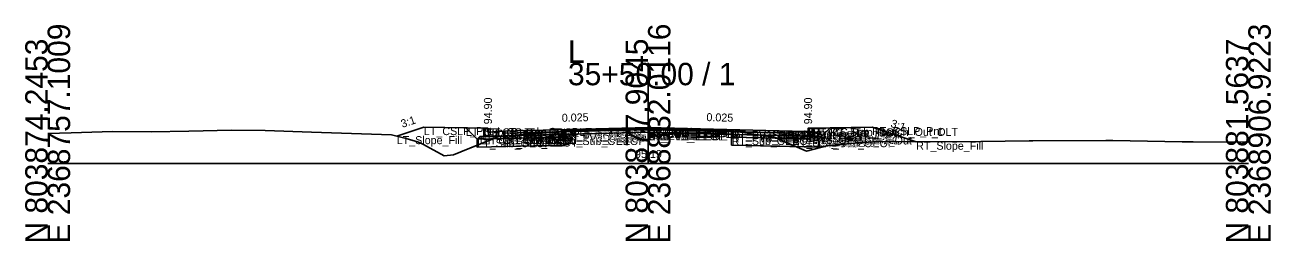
# Model space of a CAD drawing. Extents: x -26 to 8153, y -10 to 9520.
# Drawn here: x 2997.2 to 3152.8, y 990.3 to 1017.3 of the extents above; entities that cross this region are included whole.
import ezdxf

# ---------------------------------------------------------------- set-up
doc = ezdxf.new("R2010")
doc.units = 0
for name, color, linetype in [('Exist CMT Pavement', 7, 'Continuous'), ('Exist Cross Section Cell', 7, 'Continuous'), ('Exist XS Center Line Elevation Label', 7, 'Continuous'), ('Exist XS Ground Line', 7, 'Continuous'), ('Prop CMT Conc Surface', 7, 'Continuous'), ('Prop CMT Concrete Structures', 7, 'Continuous'), ('Prop CMT Pvmt Course 1', 7, 'Continuous'), ('Prop CMT Pvmt Course 1 CG', 7, 'Continuous'), ('Prop CMT Pvmt Course 1 Wedge', 7, 'Continuous'), ('Prop CMT Pvmt Course 2', 7, 'Continuous'), ('Prop CMT Pvmt Course 2 Wedge', 7, 'Continuous'), ('Prop CMT Pvmt Course 3', 7, 'Continuous'), ('Prop CMT Pvmt Course 3 Wedge', 7, 'Continuous'), ('Prop CMT Pvmt Surface', 7, 'Continuous'), ('Prop CMT Pvmt Wedge Surface 1', 7, 'Continuous'), ('Prop CMT Pvmt Wedge Surface 2', 7, 'Continuous'), ('Prop CMT Pvmt Wedge Surface 3', 7, 'Continuous'), ('Prop CMT Shallow Undercut', 7, 'Continuous'), ('Prop CMT Shallow Undercut Boundary', 7, 'Continuous'), ('Prop CMT Slope Grass', 7, 'Continuous'), ('Prop CMT Subgrade Earthwork', 7, 'Continuous'), ('Prop XS Earthwork Shape', 7, 'Continuous'), ('Prop XS Hydro Elevations', 7, 'Continuous'), ('Prop XS SE Text', 7, 'Continuous'), ('Prop XS Side Slope Text', 7, 'Continuous'), ('Prop XS Subgrade Earthwork', 7, 'Continuous'), ('Scratch_Level_2', 7, 'Continuous'), ('Scratch_Level_6', 7, 'Continuous')]:
    doc.layers.add(name, color=color, linetype=linetype)

msp = doc.modelspace()

# ---------------------------------------------------------------- linework, layer by layer
at = {"layer": 'Exist CMT Pavement'}
for p, q in [((3067.61, 1004.07), (3074.8, 1004.19)), ((3074.8, 1004.19), (3079.84, 1004.14)), ((3064.5, 1004.02), (3067.61, 1004.07)), ((3079.84, 1004.14), (3085.45, 1004.1))]:
    msp.add_line(p, q, dxfattribs=at)
at = {"layer": 'Exist Cross Section Cell'}
for p, q in [((3075, 1000), (3075, 1012.58)), ((3000, 1000), (3075, 1000)), ((3075, 1000), (3150, 1000))]:
    msp.add_line(p, q, dxfattribs=at)
at = {"layer": 'Exist XS Ground Line'}
for p, q in [((3017.62, 1004.05), (3022.95, 1004.16)), ((3022.95, 1004.16), (3027.17, 1004.12)), ((3067.61, 1004.07), (3074.8, 1004.19)), ((3074.8, 1004.19), (3079.84, 1004.14)), ((3000, 1003.75), (3002.92, 1003.84)), ((3002.92, 1003.84), (3008.08, 1003.98)), ((3008.08, 1003.98), (3012.94, 1003.94)), ((3012.94, 1003.94), (3017.62, 1004.05)), ((3027.17, 1004.12), (3032.96, 1003.91)), ((3032.96, 1003.91), (3036.72, 1003.78)), ((3036.72, 1003.78), (3042.97, 1003.59)), ((3042.97, 1003.59), (3044.78, 1003.11)), ((3044.78, 1003.11), (3046.32, 1002.68)), ((3046.32, 1002.68), (3046.95, 1002.36)), ((3051.6, 1001.44), (3056.37, 1003.39)), ((3056.37, 1003.39), (3059.85, 1003.68)), ((3059.85, 1003.68), (3064.5, 1004.02)), ((3064.5, 1004.02), (3067.61, 1004.07)), ((3079.84, 1004.14), (3085.45, 1004.1)), ((3085.45, 1004.1), (3087.95, 1003.72)), ((3087.95, 1003.72), (3090.8, 1003.31)), ((3090.8, 1003.31), (3092.17, 1002.65)), ((3092.17, 1002.65), (3094.8, 1001.55)), ((3101.3, 1002.58), (3103.05, 1002.72)), ((3103.05, 1002.72), (3103.54, 1002.74)), ((3103.54, 1002.74), (3113.06, 1002.7)), ((3113.06, 1002.7), (3113.6, 1002.71)), ((3113.6, 1002.71), (3122.63, 1002.83)), ((3122.63, 1002.83), (3123.07, 1002.83)), ((3123.07, 1002.83), (3132.18, 1002.86)), ((3132.18, 1002.86), (3133.09, 1002.87)), ((3133.09, 1002.87), (3141.72, 1002.72)), ((3141.72, 1002.72), (3143.1, 1002.71)), ((3143.1, 1002.71), (3150, 1002.68)), ((3046.95, 1002.36), (3047.31, 1002.18)), ((3047.31, 1002.18), (3049.53, 1000.94)), ((3049.53, 1000.94), (3050.72, 1001.09)), ((3050.72, 1001.09), (3051.6, 1001.44)), ((3094.8, 1001.55), (3097.51, 1002.26)), ((3097.51, 1002.26), (3101.3, 1002.58))]:
    msp.add_line(p, q, dxfattribs=at)
at = {"layer": 'Prop CMT Conc Surface'}
for points in [[(3055, 1003.9), (3055, 1004.4), (3054.5, 1004.4)], [(3095, 1003.9), (3095, 1004.4), (3095.5, 1004.4)], [(3057, 1004.03), (3055, 1003.9)], [(3093, 1004.03), (3095, 1003.9)]]:
    msp.add_lwpolyline(points, dxfattribs=at)
at = {"layer": 'Prop CMT Concrete Structures'}
for points in [[(3057, 1004.03), (3055, 1003.9), (3055, 1004.4), (3054.5, 1004.4)], [(3054.5, 1004.4), (3054.5, 1003.39), (3057, 1003.45)], [(3093, 1004.03), (3095, 1003.9), (3095, 1004.4), (3095.5, 1004.4)], [(3095.5, 1004.4), (3095.5, 1003.39), (3093, 1003.45)], [(3057, 1003.45), (3057, 1004.03)], [(3093, 1003.45), (3093, 1004.03)]]:
    msp.add_lwpolyline(points, dxfattribs=at)
at = {"layer": 'Prop CMT Pvmt Course 1'}
for points in [[(3075, 1004.48), (3057, 1004.03)], [(3064.5, 1004.1), (3075, 1004.36)], [(3075, 1004.23), (3075, 1004.48)], [(3075, 1004.48), (3093, 1004.03)], [(3075, 1004.23), (3075, 1004.48)], [(3075, 1004.36), (3075, 1004.23), (3075, 1004.23)], [(3085.45, 1004.1), (3075, 1004.36)], [(3075, 1004.36), (3075, 1004.23), (3075, 1004.23)], [(3057, 1004.03), (3057, 1003.78)], [(3057, 1003.78), (3064.5, 1003.97)], [(3064.5, 1003.97), (3064.5, 1004.1)], [(3085.45, 1003.97), (3085.45, 1004.1)], [(3093, 1003.78), (3085.45, 1003.97)], [(3093, 1004.03), (3093, 1003.78)]]:
    msp.add_lwpolyline(points, dxfattribs=at)
at = {"layer": 'Prop CMT Pvmt Course 1 CG'}
for points in [[(3057, 1003.45), (3054, 1003.38), (3053.66, 1003.04)], [(3053.66, 1003.04), (3057, 1003.12)], [(3057, 1003.12), (3057, 1003.45)], [(3093, 1003.45), (3096, 1003.38), (3096.34, 1003.04)], [(3093, 1003.12), (3093, 1003.45)], [(3096.34, 1003.04), (3093, 1003.12)]]:
    msp.add_lwpolyline(points, dxfattribs=at)
at = {"layer": 'Prop CMT Pvmt Course 1 Wedge'}
for points in [[(3075, 1004.36), (3064.5, 1004.1)], [(3075, 1004.36), (3085.45, 1004.1)]]:
    msp.add_lwpolyline(points, dxfattribs=at)
at = {"layer": 'Prop CMT Pvmt Course 2'}
for points in [[(3064.5, 1003.97), (3057, 1003.78)], [(3057, 1003.78), (3057, 1003.45)], [(3057, 1003.45), (3064.5, 1003.64)], [(3064.5, 1003.64), (3064.5, 1003.97)], [(3085.45, 1003.64), (3085.45, 1003.97)], [(3085.45, 1003.97), (3093, 1003.78)], [(3093, 1003.45), (3085.45, 1003.64)], [(3093, 1003.78), (3093, 1003.45)]]:
    msp.add_lwpolyline(points, dxfattribs=at)
at = {"layer": 'Prop CMT Pvmt Course 2 Wedge'}
for points in [[(3075, 1004.23), (3064.5, 1003.97)], [(3075, 1004.23), (3085.45, 1003.97)]]:
    msp.add_lwpolyline(points, dxfattribs=at)
at = {"layer": 'Prop CMT Pvmt Course 3'}
for points in [[(3064.5, 1003.64), (3057, 1003.45)], [(3057, 1003.45), (3057, 1003.12)], [(3057, 1003.12), (3064.5, 1003.31)], [(3064.5, 1003.31), (3064.5, 1003.64)], [(3085.45, 1003.64), (3093, 1003.45)], [(3085.45, 1003.31), (3085.45, 1003.64)], [(3093, 1003.12), (3085.45, 1003.31)], [(3093, 1003.45), (3093, 1003.12)]]:
    msp.add_lwpolyline(points, dxfattribs=at)
at = {"layer": 'Prop CMT Pvmt Course 3 Wedge'}
for points in [[(3075, 1003.9), (3064.5, 1003.64)], [(3075, 1003.9), (3085.45, 1003.64)]]:
    msp.add_lwpolyline(points, dxfattribs=at)
at = {"layer": 'Prop CMT Pvmt Surface'}
for points in [[(3075, 1004.48), (3057, 1004.03)], [(3075, 1004.48), (3093, 1004.03)]]:
    msp.add_lwpolyline(points, dxfattribs=at)
at = {"layer": 'Prop CMT Pvmt Wedge Surface 1'}
for points in [[(3075, 1004.36), (3064.5, 1004.1)], [(3075, 1004.36), (3085.45, 1004.1)], [(3057, 1003.78), (3057, 1004.03)], [(3064.5, 1003.97), (3057, 1003.78)], [(3064.5, 1004.1), (3064.5, 1003.97)], [(3085.45, 1004.1), (3085.45, 1003.97)], [(3085.45, 1003.97), (3093, 1003.78)], [(3093, 1003.78), (3093, 1004.03)]]:
    msp.add_lwpolyline(points, dxfattribs=at)
at = {"layer": 'Prop CMT Pvmt Wedge Surface 2'}
for points in [[(3075, 1004.23), (3057, 1003.78)], [(3075, 1004.23), (3093, 1003.78)], [(3057, 1003.78), (3057, 1004.03)], [(3093, 1003.78), (3093, 1004.03)]]:
    msp.add_lwpolyline(points, dxfattribs=at)
at = {"layer": 'Prop CMT Pvmt Wedge Surface 3'}
for points in [[(3057, 1003.45), (3057, 1004.03)], [(3075, 1003.9), (3057, 1003.45)], [(3075, 1003.9), (3093, 1003.45)], [(3093, 1003.45), (3093, 1004.03)]]:
    msp.add_lwpolyline(points, dxfattribs=at)
at = {"layer": 'Prop CMT Shallow Undercut'}
for points in [[(3064.5, 1002.31), (3064.5, 1003.31), (3055.64, 1003.09), (3053.66, 1002.28), (3053.66, 1002.04)], [(3092.17, 1002.65), (3093.47, 1002.11), (3085.45, 1002.31), (3085.45, 1003.31), (3091.1, 1003.17)]]:
    msp.add_lwpolyline(points, close=True, dxfattribs=at)
at = {"layer": 'Prop CMT Shallow Undercut Boundary'}
for p, q in [((3053.66, 1003.04), (3064.5, 1003.31)), ((3053.66, 1003.04), (3053.66, 1002.04)), ((3064.5, 1002.31), (3064.5, 1003.31)), ((3085.45, 1003.31), (3085.45, 1002.31)), ((3085.45, 1003.31), (3096.34, 1003.04)), ((3096.34, 1002.04), (3096.34, 1003.04)), ((3053.66, 1002.04), (3064.5, 1002.31)), ((3085.45, 1002.31), (3096.34, 1002.04))]:
    msp.add_line(p, q, dxfattribs=at)
at = {"layer": 'Prop CMT Slope Grass'}
for points in [[(3054.5, 1004.4), (3047, 1004.55), (3043.61, 1003.42)], [(3095.5, 1004.4), (3103, 1004.55), (3108.5, 1002.72)]]:
    msp.add_lwpolyline(points, dxfattribs=at)
at = {"layer": 'Prop CMT Subgrade Earthwork'}
for points in [[(3057, 1003.12), (3053.66, 1003.04), (3052.25, 1004.45)], [(3093, 1003.12), (3096.34, 1003.04), (3097.75, 1004.45)], [(3064.5, 1003.31), (3057, 1003.12)], [(3064.5, 1003.31), (3064.52, 1004.02)], [(3085.45, 1003.31), (3085.44, 1004.1)], [(3085.45, 1003.31), (3093, 1003.12)]]:
    msp.add_lwpolyline(points, dxfattribs=at)
at = {"layer": 'Prop XS Earthwork Shape'}
for points in [[(3052.25, 1004.45), (3047, 1004.55), (3043.61, 1003.42), (3044.78, 1003.11), (3046.32, 1002.68), (3046.95, 1002.36), (3047.31, 1002.18), (3049.53, 1000.94), (3050.72, 1001.09), (3051.6, 1001.44), (3053.66, 1002.28), (3053.66, 1003.04)], [(3093.47, 1002.11), (3094.8, 1001.55), (3097.51, 1002.26), (3101.3, 1002.58), (3103.05, 1002.72), (3103.54, 1002.74), (3108.5, 1002.72), (3103, 1004.55), (3097.75, 1004.45), (3096.34, 1003.04), (3096.34, 1002.04)], [(3053.66, 1002.28), (3055.64, 1003.09), (3057, 1003.12), (3064.5, 1003.31), (3064.5, 1002.31), (3053.66, 1002.04)], [(3053.66, 1002.28), (3055.64, 1003.09), (3053.66, 1003.04)], [(3064.5, 1003.31), (3057, 1003.12), (3055.64, 1003.09), (3056.37, 1003.39), (3059.85, 1003.68), (3064.5, 1004.02), (3064.52, 1004.02)], [(3085.45, 1003.31), (3091.1, 1003.17), (3090.8, 1003.31), (3087.95, 1003.72), (3085.45, 1004.1), (3085.44, 1004.1)], [(3085.45, 1003.31), (3091.1, 1003.17), (3092.17, 1002.65), (3093.47, 1002.11), (3085.45, 1002.31)], [(3093.47, 1002.11), (3096.34, 1002.04), (3096.34, 1003.04), (3093, 1003.12), (3091.1, 1003.17), (3092.17, 1002.65)]]:
    msp.add_lwpolyline(points, close=True, dxfattribs=at)
at = {"layer": 'Prop XS Subgrade Earthwork'}
for p, q in [((3053.66, 1003.04), (3064.5, 1003.31)), ((3085.45, 1003.31), (3096.34, 1003.04))]:
    msp.add_line(p, q, dxfattribs=at)
at = {"layer": 'Scratch_Level_6'}
for points in [[(3064.5, 1002.31), (3064.5, 1003.31), (3055.64, 1003.09), (3053.66, 1002.28), (3053.66, 1002.04)], [(3092.17, 1002.65), (3093.47, 1002.11), (3085.45, 1002.31), (3085.45, 1003.31), (3091.1, 1003.17)]]:
    msp.add_lwpolyline(points, close=True, dxfattribs=at)

# ---------------------------------------------------------------- texts
at = {"layer": 'Exist Cross Section Cell'}
for s, p in [('E 2368757.1009', (3002.8, 990)), ('E 2368832.0116', (3077.8, 990)), ('E 2368906.9223', (3152.8, 990)), ('N 803874.2453', (3000, 990)), ('N 803877.9045', (3075, 990)), ('N 803881.5637', (3150, 990))]:
    msp.add_text(s, height=2.8, rotation=90, dxfattribs=at).set_placement(p)
for s, p in [('L', (3065, 1012.58)), ('35+50.00 / 1', (3065, 1009.78))]:
    msp.add_text(s, height=2.8, dxfattribs=at).set_placement(p)
at = {"layer": 'Exist XS Center Line Elevation Label'}
msp.add_text('95.19', height=1, dxfattribs=at).set_placement((3073.38, 1000.69))
at = {"layer": 'Prop XS Hydro Elevations'}
for p in [(3055.5, 1004.9), (3095.5, 1004.9)]:
    msp.add_text('94.90', height=1, rotation=90, dxfattribs=at).set_placement(p)
at = {"layer": 'Prop XS SE Text'}
for rotation, p in [(1.4321, (3064.24, 1005.21)), (358.5679, (3082.29, 1005.3))]:
    msp.add_text('0.025', height=1, rotation=rotation, dxfattribs=at).set_placement(p)
at = {"layer": 'Prop XS Side Slope Text'}
for rotation, p in [(18.4349, (3044.31, 1004.45)), (341.5651, (3105.23, 1004.6))]:
    msp.add_text('3:1', height=1, rotation=rotation, dxfattribs=at).set_placement(p)
at = {"layer": 'Scratch_Level_2'}
for s, p in [('LT_CSLP_Pnt', (3047, 1003.55)), ('LT_Sub_Trench_Out_DLT', (3052.25, 1003.45)), ('LT_CG_Top_BOC', (3054.5, 1003.4)), ('LT_CG_Top_Face', (3055, 1003.4)), ('PV1_PGL', (3075, 1003.48)), ('RT_PV1_IEEOP', (3075, 1003.36)), ('LT_PV1_IEEOP', (3075, 1003.36)), ('RT_PV2_IEEOP', (3075, 1003.23)), ('LT_PV2_IEEOP', (3075, 1003.23)), ('PV2_PGL', (3075, 1003.23)), ('RT_PV_IEEOP_EG', (3075, 1003.19)), ('LT_PV_IEEOP_EG', (3075, 1003.19)), ('RT_PV_Sub_Tie_Out', (3085.44, 1003.1)), ('RT_CG_Top_Face', (3095, 1003.4)), ('RT_CG_Top_BOC', (3095.5, 1003.4)), ('RT_Sub_Trench_Out_DLT', (3097.75, 1003.45)), ('RT_CSLP_Pnt', (3103, 1003.55)), ('LT_Slope_Fill', (3043.61, 1002.42)), ('LT_Sub_OEOP', (3053.66, 1002.04)), ('LT_CG1_Shelf_Out', (3054, 1002.38)), ('LT_CG_Bot_BOC', (3054.5, 1002.39)), ('LT_CG_Top_Gut', (3055, 1002.9)), ('LT_PV1_OEOT', (3057, 1003.03)), ('LT_PV2_OEOT', (3057, 1002.78)), ('LT_PV3_OEOT', (3057, 1002.45)), ('LT_CG_Bot_IE', (3057, 1002.45)), ('LT_Sub_OEOT', (3057, 1002.12)), ('LT_PV1_OEEOP', (3064.5, 1003.1)), ('LT_PV_OEEOP_EG', (3064.5, 1003.02)), ('LT_PV2_OEEOP', (3064.5, 1002.97)), ('LT_PV3_OEEOP', (3064.5, 1002.64)), ('LT_Sub_OEEOP', (3064.5, 1002.31)), ('LT_PV_Sub_Tie_Out', (3064.52, 1003.02)), ('RT_PV3_IEEOP', (3075, 1002.9)), ('LT_PV3_IEEOP', (3075, 1002.9)), ('RT_PV_OEEOP_EG', (3085.45, 1003.1)), ('RT_PV1_OEEOP', (3085.45, 1003.1)), ('RT_PV2_OEEOP', (3085.45, 1002.97)), ('RT_PV3_OEEOP', (3085.45, 1002.64)), ('RT_Sub_OEEOP', (3085.45, 1002.31)), ('RT_PV1_OEOT', (3093, 1003.03)), ('RT_PV2_OEOT', (3093, 1002.78)), ('RT_PV3_OEOT', (3093, 1002.45)), ('RT_CG_Bot_IE', (3093, 1002.45)), ('RT_Sub_OEOT', (3093, 1002.12)), ('RT_CG_Top_Gut', (3095, 1002.9)), ('RT_CG_Bot_BOC', (3095.5, 1002.39)), ('RT_CG1_Shelf_Out', (3096, 1002.38)), ('RT_Sub_OEOP', (3096.34, 1002.04)), ('RT_Slope_Fill', (3108.5, 1001.72))]:
    msp.add_text(s, height=1, dxfattribs=at).set_placement(p)

doc.saveas('drawing.dxf')
